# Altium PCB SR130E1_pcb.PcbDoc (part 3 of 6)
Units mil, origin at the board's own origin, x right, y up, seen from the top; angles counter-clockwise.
Board outline 5700 x 4800 mil, 6 copper layers (Top Layer, Signal Layer 1, Signal Layer 2, Signal Layer 3, Signal Layer 4, Bottom Layer), stack 61.4 mil thick; 452 components, 288 nets, 1391 pads, 911 vias.
Unrouted connection lines stored in the file: 523.
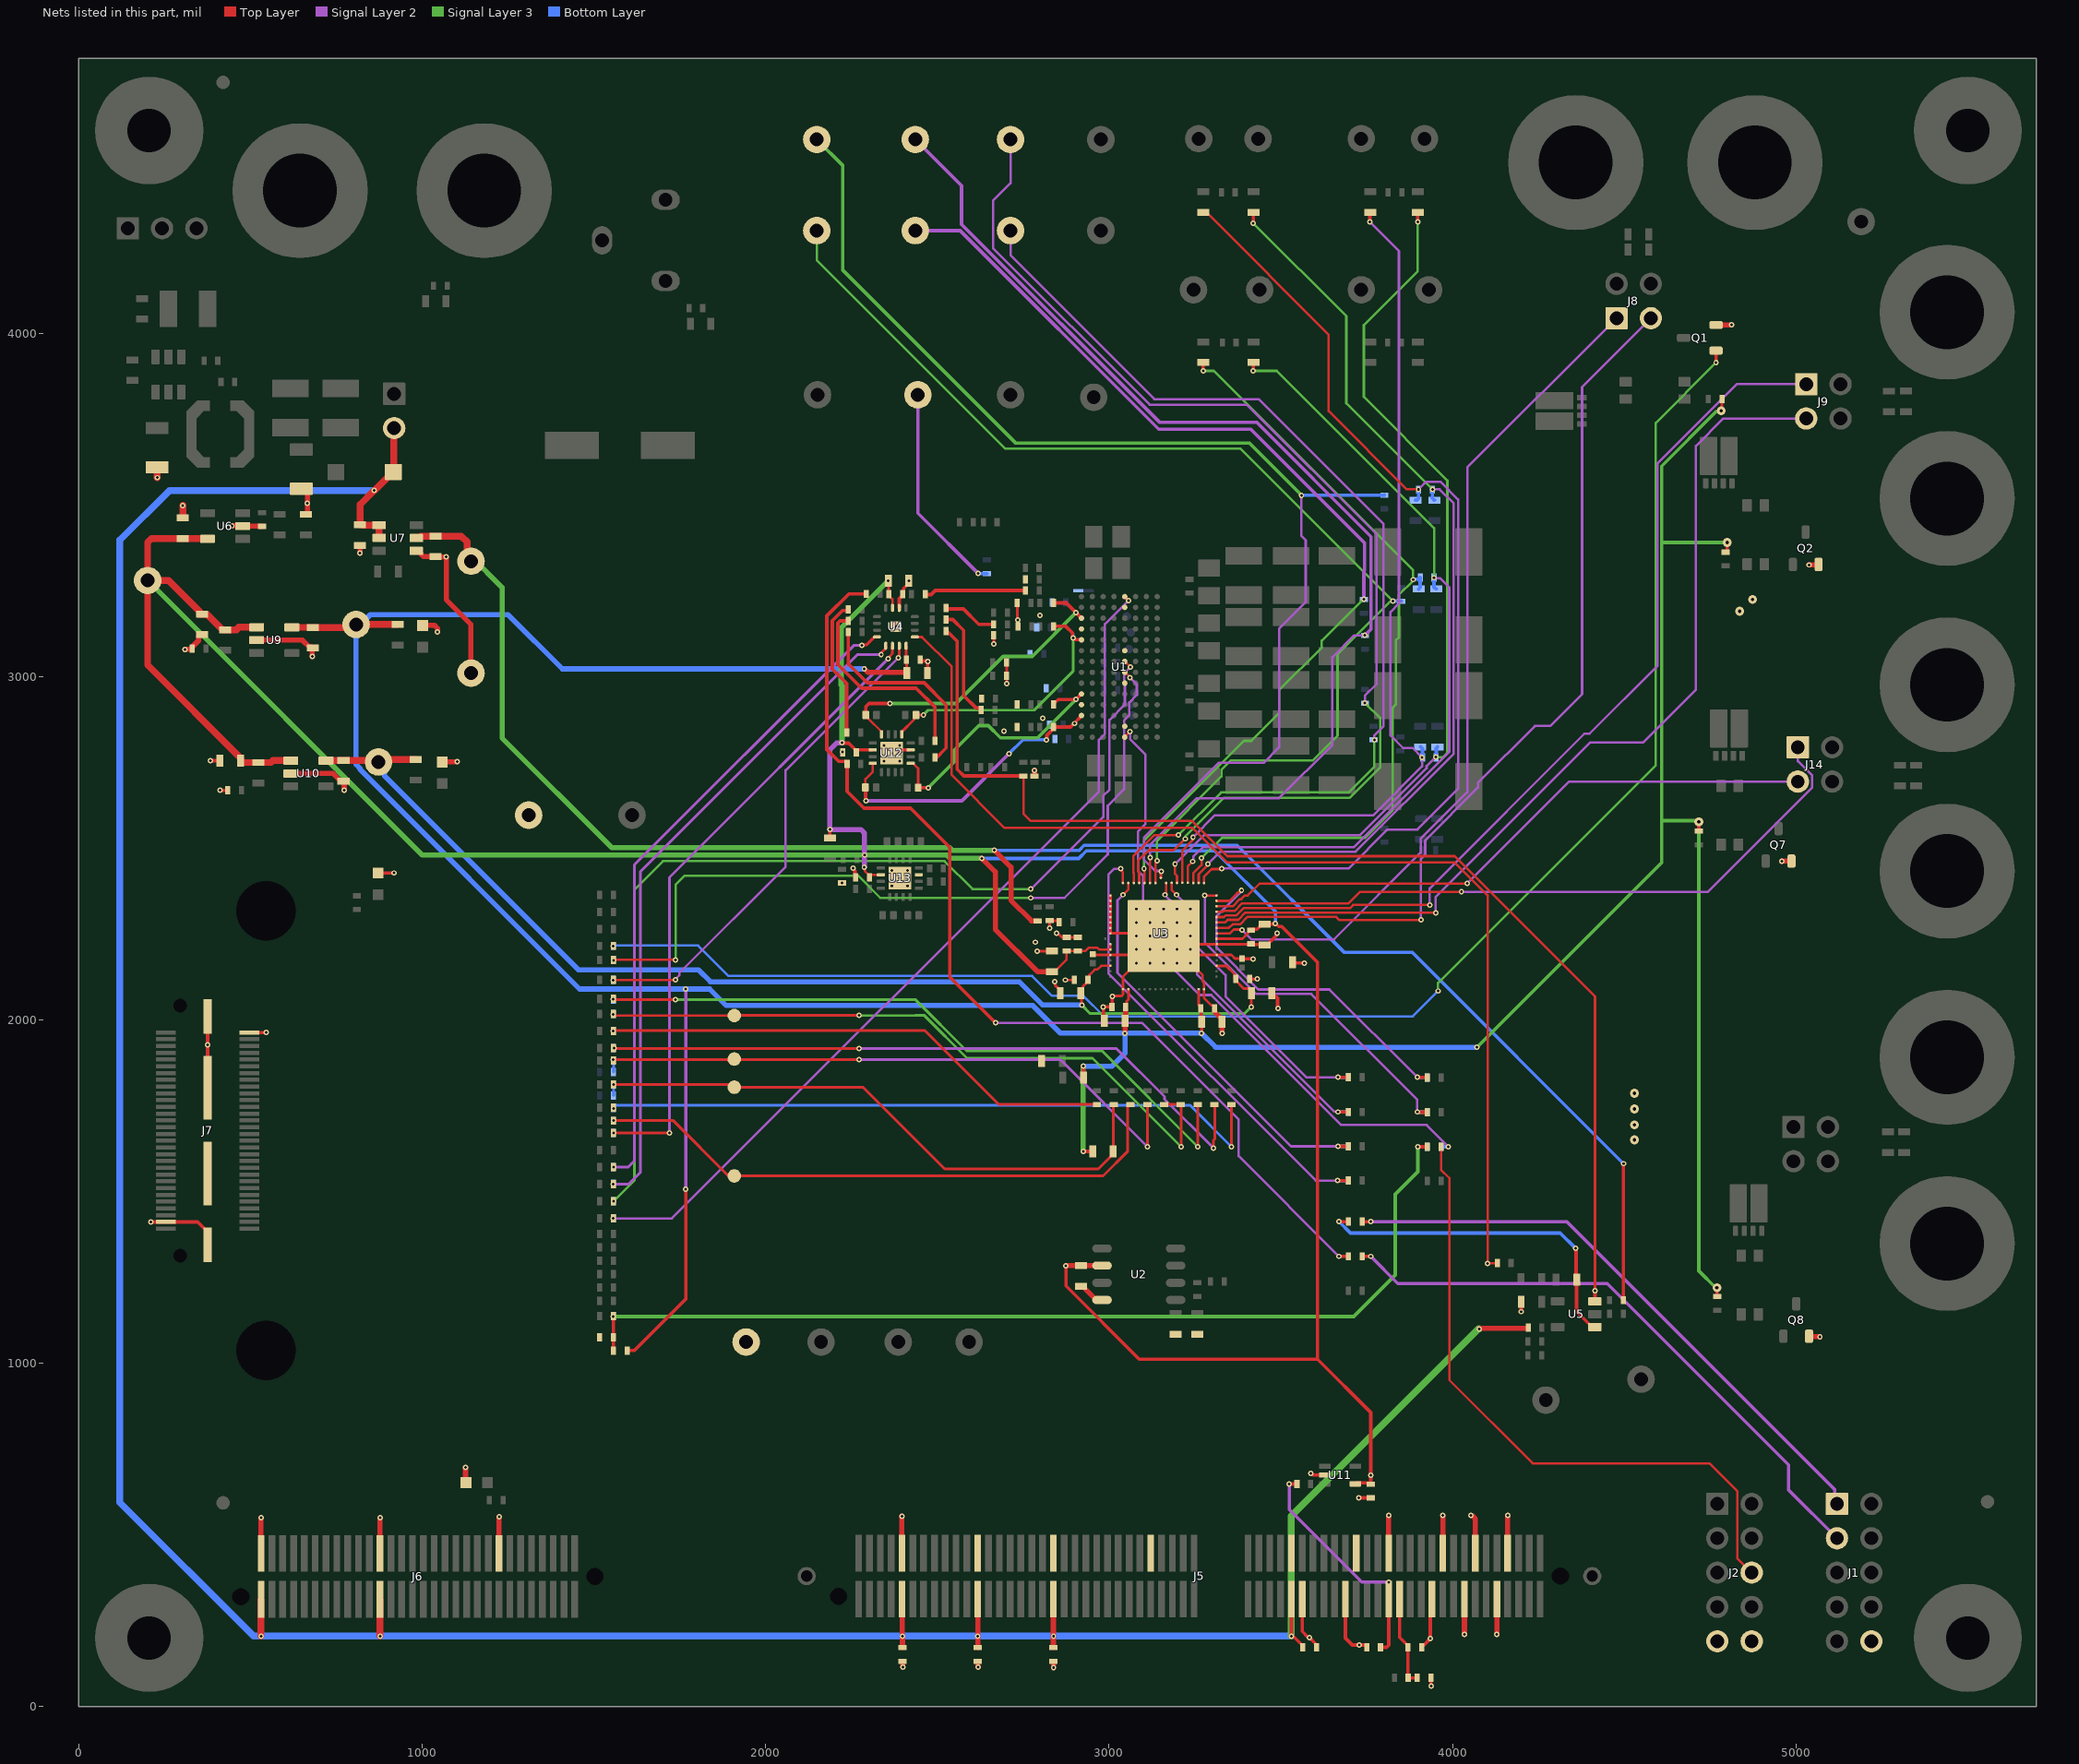
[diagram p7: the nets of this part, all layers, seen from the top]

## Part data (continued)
R116 R117 R118 R119 R120 R121 R122 R123 R124 R125 R126 R127 R128 R129 R130 R131 R132 R133 R134 R135 R136 R138 R139 R140 R141 R142 R143 R144 R145 R149 R150 R151 R152 R153 R154 R155 R156 R157 R158 R159 R160 R161 R162 R163 R164 R165 R166 R167 R168 R170 R171 R172 R173 R174 R175 R176: library part CMP-0026880-3, "RES, 22, 5%, 0.063 W, AEC-Q200 Grade 0, 0402", Manufacturer=Vishay-Dale, Power_W=63mW, Supplier Part Number 1=541-22JCT-ND, TempCo="200 ppm/C", Tolerance_%=5%, Value2=0.063W, Value_Code=22R0, ValueDisplayed=22
R137 R147 R148 R169: library part CMP-0026770-1, "RES, 1.00 k, 0.1%, 0.063 W, 0402", Manufacturer=Panasonic, Power_W=63mW, Supplier Part Number 1=P1.0KDCCT-ND, TempCo="25 ppm/C", Tolerance_%=0.1%, Value2=0.063W, Value_Code=1k00, ValueDisplayed=1.00k
R146: library part CMP-0026805-1, "RES, 2.74 k, 0.1%, 0.063 W, 0402", Manufacturer="TT Electronics/IRC", Power_W=63mW, TempCo="10 ppm/C", Tolerance_%=0.1%, Value2=0.063W, Value_Code=2k74, ValueDisplayed=2.74k
R179 R180 R181 R182: library part CMP-0026022-3, "RES, 150, 1%, 0.063 W, AEC-Q200 Grade 0, 0402", Manufacturer=Vishay-Dale, Power_W=63mW, Supplier Part Number 1=541-150LCT-ND, TempCo="100 ppm/C", Tolerance_%=1%, Value2=0.063W, Value_Code=150R, ValueDisplayed=150
R188: library part CMP-0026581-2, "RES, 866, 1%, 0.063 W, AEC-Q200 Grade 0, 0402", Manufacturer=Vishay-Dale, Power_W=63mW, Supplier Part Number 1=541-866LCT-ND, TempCo="100 ppm/C", Tolerance_%=1%, Value2=0.063W, Value_Code=866R, ValueDisplayed=866
SH-J1 SH-J2 SH-J3 SH-J4 SH-J5 SH-J6 SH-J7 SH-J8 SH-J9 SH-J10: library part CMP-0003761-2, "Shunt, 2.54mm, Gold, Black", Manufacturer="Wurth Elektronik", Supplier Part Number 1=732-2678-ND
TP1 TP5 TP8 TP12 TP26 TP27 TP29 TP30 TP31 TP32: library part CMP-0055137-2, "Test Point, Miniature, Red, TH", Color=Red, Manufacturer="Keystone Electronics", Supplier Part Number 1=36-5000-ND
TP2 TP6 TP9 TP10 TP11 TP13 TP18 TP19 TP20 TP21 TP28 TP33 TP34 TP35 TP36 TP37 TP38: library part CMP-0055138-2, "Test Point, Miniature, Black, TH", Color=Black, Manufacturer="Keystone Electronics", Supplier Part Number 1=36-5001-ND
TP3 TP7 TP14 TP15 TP16 TP17: library part CMP-0055141-2, "Test Point, Miniature, Yellow, TH", Color=Yellow, Manufacturer="Keystone Electronics", PartNumber=5004, Supplier Part Number 1=36-5004-ND
TP4: library part CMP-0055138-2, "Test Point, Miniature, Black, TH", Color=Black, Manufacturer="Keystone Electronics", PartNumber=5001, Supplier Part Number 1=36-5001-ND
TP22 TP23 TP24 TP25: library part CMP-0003825-1, "1mm Test Point, SMT", Manufacturer=Any
U1: library part CMP-0123459-1, Manufacturer="Texas Instruments", Operating Temperature Range=to
U2: library part CMP-0032601-1, "Low Noise, Very Low Drift, Precision Voltage Reference, -40 to 125 degC, 8-pin SOIC (D), Green (RoHS & no Sb/Br)", Manufacturer="Texas Instruments", Rating=Catalog, Temp Coeff(Max)(ppm/ degree C)=3
U3: library part CMP-0124125-1, "16-Channel, 16-Bit, 1-MSPS Simultaneous-Sampling SAR ADC with Bipolar Inputs on a Single Supply", Manufacturer="Texas Instruments", Max Supply Voltage=5.25V, Min Supply Voltage=1.75V, Operating Temperature Range="-40°C to +125°C"
U4: library part CMP-0084837-1, "8-Channel, True 16-Bit, SPI, Voltage-Output DAC With Precision Internal Reference, RTE0016D (WQFN-16)", Alternate Manufacturer="Texas Instruments", Alternate PartNumber=DAC80508MRTER, Operating Temperature Range="-40 to 125 C", Rating=Catalog
U5: library part CMP-0040539-2, "Precision, Rail-to-Rail Input/Output, Low Offset Voltage, Low Input Bias Current Op Amp with E-trim, 4.5 to 36 V, -40 to 125 degC, 8-Pin SOT-23 (DBV), Green (RoHS & no Sb/Br), Tape and Reel", Temperature Max="125 degC", Temperature Min="-40 degC"
U6: library part CMP-0091339-1, "300-mA, ultra-low-noise, low-IQ, low-dropout (LDO) linear regulator with high PSRR 5-SOT-23 -40 to 125", Dropout Voltage=140mV, Manufacturer="Texas Instruments", Max Supply Voltage=6V, Min Supply Voltage=1.6V, Mouser Part Number=595-TPS7A2050PDBVR, Nominal Supply Current=6.5uA, Operating Temperature Range="-40°C to +125°C", Output Voltage=5V
U7: library part CMP-0072146-1, "Switched Capacitor Voltage Converter, 6-pin SOT-23", Manufacturer="Texas Instruments", PackageTopMarking=S03A*XTT, PartNumber=LM2664M6/NOPB, PowerWise=N
U8: library part CMP-0093105-2, "Buck Converter, Adjustable, 4V-36V Input, 1-28V 1A Output, SOT23-6", Manufacturer="Texas Instruments", Max Supply Voltage=36V, Min Supply Voltage=4V, Nominal Supply Current=80uA, Operating Temperature Range="-40°C to +150°C", Output Voltage=1-28V, Switching Frequency=700kHz
U9: library part CMP-0092532-1, "300-mA, Ultra-Low-Noise, Low-IQ, High PSRR LDO", Digikey Part Number=296-TPS7A2033PDBVRCT-ND, Dropout Voltage=145mV, Manufacturer="Texas Instruments", Max Supply Voltage=6V, Min Supply Voltage=1.6V, Mouser Part Number=595-TPS7A2033PDBVR, Nominal Supply Current=6.5uA, Operating Temperature Range="-40°C to +125°C", Output Voltage=3.3V
U10: library part CMP-0095212-1, "Linear Voltage Regulator IC Positive Fixed 1 Output 300mA SOT-23-5", Digikey Part Number=296-TPS7A2018PDBVRCT-ND, Dropout Voltage=690mV, Manufacturer="Texas Instruments", Max Supply Voltage=6V, Min Supply Voltage=1.6V, Mouser Part Number=595-TPS7A2018PDBVR, Nominal Supply Current=6.5-2000uA, Operating Temperature Range="-40°C to +125°C", Output Voltage=1.8V
U11: library part CMP-0013250-3, "TMP235DCK, DCK0005A (SOT-5)", Manufacturer="Texas Instruments"
U12 U13: library part CMP-0123533-1, "Quad 1-MHz, 40-V rail-to-rail input/output, low-offset-voltage, low-power op amp 16-WQFN -40 to 125", Digikey Part Number=296-OPA4990IRTERCT-ND, Input Bias Current=10pA, Input Offset Voltage=0.3mV, Manufacturer="Texas Instruments", Max Dual Supply Voltage=20V, Max Supply Voltage=40V, Min Dual Supply Voltage=1.35V, Min Supply Voltage=2.7V, Mouser Part Number=595-OPA4990IRTER, Nominal Supply Current=120uA, Operating Temperature Range="-40°C to +125°C", Output Current Per Channel=80mA, Voltage Gain=145dB
ZZ1: library part CMP-0003616-3
ZZ2: library part CMP-0077236-1
ZZ3: library part CMP-0077237-1
ZZ4: library part CMP-0077238-1

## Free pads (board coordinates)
  round 25 smd far side mask+1.97: 2(3052.27,3175.01) 2(3057.91,3079.86) 2(3063.58,3128.37) 2(3065.52,2919.41) 2(3067.43,2886.51) 2(3073.81,2951.75)

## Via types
v1: diameter 26, hole 10, Top Layer to Bottom Layer, tented both sides, 435 vias
v2: diameter 16, hole 8, Top Layer to Bottom Layer, tented both sides, 208 vias
v3: diameter 16, hole 8, Top Layer to Bottom Layer, 145 vias
v4: diameter 16, hole 8, Top Layer to Bottom Layer, tented bottom, 46 vias
v5: diameter 19.68, hole 8, Top Layer to Bottom Layer, tented both sides, 35 vias
v6: diameter 17, hole 8, Top Layer to Bottom Layer, 30 vias
v7: diameter 18, hole 8, Top Layer to Bottom Layer, tented both sides, 6 vias
v8: diameter 16, hole 8, Top Layer to Bottom Layer, tented top, 4 vias
v9: diameter 19.68, hole 8, Top Layer to Bottom Layer, 1 vias
v10: diameter 17, hole 8, Top Layer to Bottom Layer, tented both sides, 1 vias

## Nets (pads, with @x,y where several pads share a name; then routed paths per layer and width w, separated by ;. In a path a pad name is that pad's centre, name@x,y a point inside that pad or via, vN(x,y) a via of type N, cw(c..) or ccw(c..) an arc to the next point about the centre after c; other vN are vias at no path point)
1V8A: C80.2 C81.2 C82.2 C83.1 C108.1 R115.2 TP32.1 U3.30 U3.51 U10.5 | length 3491.6
  Top Layer w7: C81.2@2938.7,2116.06 2942.7,2120.06 2942.7,2130.43 2958.78,2146.51 2966.03,2146.51 2976.97,2157.44 U3.30@3004.17,2157.44
  Top Layer w8: v3@2920.24,2042.59 v3(2920.7,2043.06) 2919.41,2044.34 2919.41,2076.55 C82.2@2918.12,2077.84 2924.12,2083.84 2924.12,2096.98 2938.7,2111.56 C81.2@2938.7,2116.06 ; U3.51@3313.22,2157.44 3341.14,2157.44 3365.55,2133.03 3365.55,2117.73 3392.73,2090.55 3408.45,2090.55 3414.45,2084.55 C83.1@3414.45,2077.05 3414.09,2076.68 3414.09,2038.01 v3(3413.73,2037.65)
  Top Layer w20: U10.5@720.06,2754.8 763.55,2754.8 C108.1@771.06,2754.82 869.02,2754.82 TP32.1@872.97,2750.87 880.34,2758.23 R115.2@981.48,2758.23
  Signal Layer 3 w8: v3(2920.7,2043.06) 2945.7,2018.06 3394.13,2018.06 v3(3413.73,2037.65)
  Bottom Layer w15: TP32.1@872.97,2750.87 872.97,2733.28 890.58,2715.67 890.58,2710.08 1455.16,2145.5 1804.53,2145.5 1839.22,2110.81 2738.75,2110.81 2806.5,2043.06 v3(2920.7,2043.06)
3V3D: C71.2 C74.2 C76.2 C77.2 C90.1 C91.2 C103.1 R86.1 R88.2 R111.2 R178.2 R179.2 R180.2 R181.2 R182.2 TP31.1 U3.34 U3.47 U4.16 U9.5 | length 11955.4
  Top Layer w7: U3.47@3261.06,2089.53 3261.06,2043.59 3267,2037.65 C76.2@3267,2033.15
  Top Layer w8: U4.16@2409,3089.49 2409.28,3089.21 2409.28,3049.85 C90.1@2410.29,3048.84 2410.72,3048.41 2410.72,3010.42 C91.2@2411.15,3009.99 ; C77.2@3048.63,2037.84 3052.13,2041.34 3052.13,2054.62 3056.34,2058.83 U3.34@3056.34,2089.53 ; v1(4782.65,3773.82) 4783.94,3775.12 4783.94,3806.94 R179.2@4785.24,3808.24
  Top Layer w10: R178.2@1597.16,1036.74 1599.29,1036.74 1599.66,1037.1 1617.8,1037.1 1767.74,1187.04 v3(1767.74,1506.65) ; v2(2924.73,1616.77) R88.2@2952.43,1616.77 ; v2(2924.76,1864.81) 2925.05,1864.52 2925.05,1831.72 R86.1@2925.34,1831.43 ; C76.2@3267,2033.15 3268.22,2031.93 3268.22,1995.14 C74.2@3269.45,1993.92 3269.57,1993.79 3269.57,1961.18 v2(3269.7,1961.06) ; R181.2@4717.32,2549.51 v1(4717.32,2576.97) ; v1(4770,1220) 4770.51,1219.49 4770.51,1195.07 R182.2@4771.02,1194.56 ; R180.2@4794.85,3362.02 4797.5,3362.02 4800,3364.52 v1(4800,3390)
  Top Layer w15: v4(2287.75,3021.94) 2288.02,3021.94 2298.02,3011.93 2408.65,3011.93 2410.16,3010.42 C91.2@2410.72,3010.42 ; v2(3046.7,1961.06) C71.2@3046.7,1997.06 3048.63,1998.99 C77.2@3048.63,2037.84
  Top Layer w20: U9.5@620.56,3143.26 620.82,3143 681.75,3143 C103.1@682.01,3142.73 799.1,3142.73 TP31.1@807.72,3151.35 921.5,3151.35 921.88,3151.73 R111.2@929.38,3151.73
  Signal Layer 2 w10: v3(1767.74,1506.65) v2(1767.74,2089.81)
  Signal Layer 3 w10: v2(4070.97,1920) 4608.97,2458 4608.97,2580 ; v1(4770,1220) 4766.14,1220 4717.32,1268.83 4717.32,2170.52 v1(4717.32,2576.97) 4715.21,2579.07 4707.43,2579.07 4706.51,2580 4608.97,2580 ; v1(4782.65,3773.82) 4779.58,3770.76 4767.14,3770.76 4608.97,3612.59 4608.97,3390 ; v1(4800,3390) 4608.97,3390 ; 4608.97,2580 4608.97,3390
  Signal Layer 3 w15: v2(2924.73,1616.77) v2@2924.75,1864.79
  Bottom Layer w15: v4(2287.75,3021.94) 1408.06,3021.94 1250,3180 849.01,3180 820.36,3151.35 TP31.1@807.72,3151.35 807.72,2743.99 819.47,2732.24 819.47,2728.71 1458.37,2089.81 1837.59,2089.81 1885.56,2041.84 2778.01,2041.84 2858.8,1961.06 v2(3046.7,1961.06) ; v2(2924.76,1864.81) 3008.09,1864.81 3046.7,1903.42 v2(3046.7,1961.06) ; v2(4070.97,1920) 3310.75,1920 v2(3269.7,1961.06) v2(3046.7,1961.06)
5V2: C95.2 C112.2 C113.2 C114.2 C115.2 J4.2 J5.48 J5.84 J5.98 J5.112 J6.158 J6.180 L1.1 R102.2 U7.4 U7.5 | length 9656.3
  Top Layer w10: J5.112@2397.12,313.07 J5.112@2397.93,312.27 ; C115.2@2397.93,173 C115.2@2398.73,172.2 ; J5.98@2617.6,313.07 J5.98@2617.81,312.86 ; C114.2@2617.81,172.41 C114.2@2618.02,172.2 ; C113.2@2837.69,172.2 C113.2@2837.88,172.39 ; J5.84@2837.88,312.88 J5.84@2838.07,313.07 ; J5.48@3530.98,313.07 3530.98,205.61 3532.13,204.47 3536.87,204.47 3564.24,177.1 C112.2@3564.24,173.04 ; v2(4078.15,1100) v2@4079.3,1101.15 ; R102.2@4217.95,1101.15 4220.45,1103.65 R102.2@4220.45,1104
  Top Layer w15: C115.2@2397.93,172.2 2398.6,172.2 2398.6,205.34 2398.28,205.66 2398.28,311.91 J5.112@2397.93,312.27 ; C114.2@2617.81,172.2 C114.2@2618.02,172.2 v2(2618.02,205.34) 2617.83,205.53 J5.98@2617.83,312.83 ; C113.2@2837.88,172.2 2837.88,204.39 2838.56,205.07 2838.56,205.61 2837.88,206.3 J5.84@2837.88,312.88 ; v2@4079.3,1101.15 R102.2@4217.95,1101.15
  Top Layer w20: v2(531.13,205.5) J6.180@531.13,312.2 ; U7.5@874.95,3403.33 U7.4@874.95,3440.73 827.13,3440.73 826.59,3441.28 C95.2@819.09,3441.28 819.09,3500.38 v2(860.22,3541.51) 861.05,3541.51 915.06,3595.53 L1.1@916.05,3595.53 917.35,3596.83 917.35,3721.88 J4.2@918.65,3723.18 ; v2(877.59,205.5) J6.158@877.59,312.2
  Signal Layer 3 w20: v2(3530.71,205.34) 3530.71,555.3 4075.41,1100 v2(4078.15,1100)
  Bottom Layer w20: v2(860.22,3541.51) 264.55,3541.51 120,3396.97 120,594.56 509.06,205.5 v2(877.59,205.5) ; v2(877.59,205.5) v2(2398.47,205.47) 2398.66,205.34 v2(2618.02,205.34) v2(2838.56,205.34) v2(3530.71,205.34) v2@3530.98,205.61
5VA: C68.1 C70.1 C73.2 C75.2 C78.2 C79.2 C88.2 C89.1 C94.1 C98.1 C106.1 C109.2 C126.2 C127.2 R108.1 R114.1 R187.1 TP29.1 U2.2 U3.26 U3.27 U3.56 U4.7 U6.5 U9.1 U10.1 U11.4 U12.2 U13.2 | length 10156.2
  Top Layer w7: v2(2287.75,2444.27) 2288.89,2443.13 2288.89,2433.64 2302.79,2419.74 C127.2@2302.79,2415.24 2302.79,2418.62 2306.79,2422.62 U13.2@2335.79,2422.62 ; v4(2357.09,3278.87) 2358.28,3277.68 2358.28,3240.95 C89.1@2359.47,3239.75 2359.47,3235.25 2369.63,3225.1 U4.7@2369.63,3199.73 ; C70.1@2841.2,2140.06 2869.39,2168.25 2876.37,2175.23 C78.2@2876.37,2200.07 C79.2@2908.8,2200.07 ; C79.2@2907.4,2198.67 C79.2@2908.8,2200.07 ; U3.26@3004.17,2220.43 U3.27@3004.17,2204.68 2971.23,2204.69 2966.31,2209.6 2940.49,2209.6 2930.96,2200.07 C79.2@2908.8,2200.07
  Top Layer w8: U3.56@3313.22,2236.18 3388.47,2236.18 3405.63,2253.35 3405.63,2257.85 3409.13,2261.35 C75.2@3413.63,2261.35
  Top Layer w10: R187.1@2187.16,2529.47 2187.27,2529.58 v2(2187.27,2554.06) ; v2(2222.65,2806.74) 2223.8,2805.6 2242.39,2805.6 2261.72,2786.27 2261.72,2781.77 C126.2@2264.22,2779.27 ; C126.2@2264.41,2779.08 2264.41,2783.73 2266.72,2786.04 2311.91,2786.04 U12.2@2312.18,2786.32 ; v3(2874.65,1283.83) 2874.65,1225.18 3088.14,1011.7 3606.81,1011.7 ; C75.2@3409.13,2261.35 3411.63,2263.85 3430.99,2263.85 3445.2,2278.05 C73.2@3452.7,2278.05 3453.65,2279 3483.54,2279 v3(3484.49,2279.95) 3486.12,2279.95 3494.35,2271.71 3502.74,2271.71 3548.56,2225.9 3606.81,2167.64 3606.81,1011.7 ; U11.4@3717.33,648.67 3720.2,651.54 C109.2@3761.88,651.54 ; C109.2@3761.88,648.03 C109.2@3761.88,651.54 ; 3606.81,1011.7 3761.88,856.63 v3(3761.88,674.26) C109.2@3761.88,651.54
  Top Layer w15: v3(2629.69,2470.18) 2668.98,2430.89 2668.98,2263.3 2792.22,2140.06 C70.1@2841.2,2140.06 ; v3(2874.65,1283.83) 2874.69,1283.87 2918.94,1283.87 2919.09,1284.02 2979.57,1284.02 U2.2@2979.68,1284.14
  Top Layer w20: U6.5@375.14,3400.62 373.67,3402.1 C94.1@303.39,3402.1 212.5,3402.1 200.79,3390.38 TP29.1@200.79,3279.56 ; U9.1@518.19,3143.26 466.54,3143.26 459.14,3135.86 R108.1@426.32,3135.86 418.82,3135.86 372.95,3181.73 C98.1@359.28,3181.73 351.78,3181.73 351.78,3189.23 261.44,3279.56 TP29.1@200.79,3279.56 ; U10.1@617.7,2754.8 566.04,2754.8 560.61,2749.37 R114.1@522.97,2749.37 471.61,2749.37 C106.1@471.61,2754.8 471.61,2762.3 200.79,3033.12 TP29.1@200.79,3279.56
  Signal Layer 2 w15: v2(2222.65,2806.74) 2207.43,2806.74 2187.27,2786.58 v2(2187.27,2554.06) 2277.34,2554.06 2287.87,2543.53 v2(2287.87,2479.98) 2287.81,2479.92 2287.81,2444.34 v2(2287.75,2444.27)
  Signal Layer 3 w15: TP29.1@200.79,3279.56 1000.37,2479.98 v2(2287.87,2479.98) ; v2(2222.65,2806.74) 2222.65,2973.07 2220,2975.73 2220,3141.78 v4(2357.09,3278.87) ; v2@2287.87,2480.44 2288.33,2479.98 2527.8,2479.98 2537.6,2470.18 v3(2629.69,2470.18)
  Bottom Layer w10: v3(2629.69,2470.18) 2912.11,2470.18 2933.94,2492.01 3307.64,2492.01 3484.49,2315.16 v3(3484.49,2279.95)
-5V: C101.2 R89.2 R106.2 TP30.1 U7.2 | length 5241.2
  Top Layer w10: R106.2@4497.78,1183.62 v2(4497.78,1581.22)
  Top Layer w15: v4(2665.57,2493.68) 2714.7,2444.55 2714.7,2348.01 2774.4,2288.31 R89.2@2792.79,2288.31
  Top Layer w20: U7.2@983.22,3403.33 991.09,3403.33 996.56,3408.8 C101.2@1039.09,3408.8 1114.09,3408.8 1130.91,3391.98 1130.91,3346.99 TP30.1@1142.39,3335.51
  Signal Layer 3 w15: TP30.1@1142.39,3349.89 1232.99,3259.28 1232.99,2821.04 1552.56,2501.48 2536,2501.48 2543.8,2493.68 v4(2665.57,2493.68)
  Bottom Layer w10: v4(2665.57,2493.68) 2912.98,2493.68 2927.31,2508.01 3373.24,2508.01 3684.41,2196.84 3882.15,2196.84 v2(4497.78,1581.22)
ADC_CONVST: R83.2 R139.2 R156.1 | length 1975.5
  Top Layer w8: R156.1@1557.16,1744.16 R156.1@1558.97,1742.35 ; R83.2@3355.89,1753.45 3356.48,1752.86 v4(3356.48,1630.49)
  Bottom Layer w8: R139.2@1558,1748.99 1560.66,1751.65 3235.31,1751.65 v4(3356.48,1630.49)
  other v3: 1557.99,1741.38
ADC_CSn: R79.2 R88.1 R123.1 R126.1 R157.1 TP25.1 | length 1757.3
  Top Layer w8: R157.1@1557.09,1811.96 v3(1557.16,1811.96) ; R157.1@1557.16,1807.4 v3(1557.16,1811.96) ; R79.2@3013.73,1753.45 3012.43,1752.15 R88.1@3012.43,1616.77 3012.43,1609.27 2968.83,1565.67 2521.74,1565.67 2283.75,1803.66 1900.45,1803.66 1892.14,1811.96 v3(1557.16,1811.96)
  Bottom Layer w8: R123.1@1557.16,1779.39 v3(1557.16,1811.96)
ADC_DRDY: R82.2 R127.1 R159.1 | length 2003.5
  Top Layer w8: R159.1@1557.16,1917.93 1558.4,1916.69 v3(2271.94,1916.69) ; v4(3303.75,1626.64) 3303.75,1648.8 3307.6,1652.64 3307.6,1752.86 R82.2@3307.01,1753.45
  Signal Layer 2 w8: v3(2271.94,1916.69) 3021.39,1916.69 3161.42,1776.66 3161.42,1768.97 v4(3303.75,1626.64)
  Bottom Layer w8: R127.1@1558.13,1918.91 R127.1@1560.34,1916.69
  other v3: 1559.24,1917.8
ADC_RSTn: R84.2 R128.1 R160.1 | length 1497.2
  Top Layer w8: R160.1@1557.16,1967.49 1558.13,1968.46 1730,1968.46 2464.62,1968.46 2679.63,1753.45 R84.2@2964.85,1753.45
  other v3: 1556.67,1967
ADC_SCLK: R76.2 R122.1 R125.1 R158.1 TP22.1 | length 1813.8
  Top Layer w8: R158.1@1556.32,1883.86 1888.57,1883.86 TP22.1@1897.87,1874.56 ; TP22.1@1908.94,1885.63 1909.82,1884.75 2271.06,1884.75 v3(2271.94,1883.86) ; R76.2@3111.49,1753.45 3112.08,1752.86 v4(3112.08,1630.49)
  Signal Layer 2 w8: v3(2271.94,1883.86) 2858.7,1883.86 v4(3112.08,1630.49)
  Bottom Layer w8: R122.1@1557.16,1847.46 R125.1@1557.16,1883.86
  other v3: 1556.9,1883.86
ADC_SDI: R77.2 R120.1 R155.1 TP23.1 | length 1736.8
  Top Layer w8: R155.1@1557.16,1706.1 1558.3,1707.24 1730,1707.24 1891.78,1545.46 2982.77,1545.46 3054.61,1617.31 3054.61,1749.95 3058.11,1753.45 R77.2@3062.61,1753.45
  other v3: 1557.43,1706.27
ADC_SDOA: R78.2 R81.2 R121.1 R161.1 TP24.1 | length 1991.4
  Top Layer w8: R161.1@1557.16,2017.05 R161.1@1557.16,2016.05 ; R161.1@1560.66,2012.55 R161.1@1557.16,2016.05 ; v4(2271.94,2012.55) 1908.98,2012.53 TP24.1@1908.94,2012.51 1560.66,2012.48 1557.16,2015.98 R161.1@1557.16,2016.05 ; R78.2@3160.96,1752.86 R78.2@3160.37,1753.45 R81.2@3209.25,1753.45 3209.84,1752.86 v4(3209.84,1630.49)
  Signal Layer 3 w8: v4(2271.94,2012.55) 2272,2012.48 2436.76,2012.48 2436.83,2012.55 2462.58,2012.55 2586.66,1888.47 2951.85,1888.47 v4(3209.84,1630.49)
  other v3: 1556.18,2016.07
ADC_SDOB: R80.2 R124.1 R162.1 | length 2002.3
  Top Layer w8: R162.1@1557.16,2059.2 v4(1738,2059.2) ; R80.2@3258.13,1753.45 3258.72,1752.86 v4(3258.72,1630.49)
  Signal Layer 3 w8: v4(1738,2059.2) 2435.73,2059.2 2585.37,1909.56 2979.64,1909.56 v4(3258.72,1630.49)
  other v3: 1556.18,2059.96
AGND: C1.2 C2.2 C3.2 C4.2 C9.2 C11.2 C12.2 C17.2 C68.2 C69.2 C70.2 C71.1 C72.2 C73.1 C74.1 C75.1 C76.1 C77.1 C78.1 C79.1 C80.1 C81.1 C82.1 C83.2 C84.1 C85.2 C86.2 C87.2 C88.1 C89.2 C90.2 C91.1 C92.2 C93.1 C94.2 C95.1 C98.2 C100.1 C101.1 C103.2 C106.2 C107.1 C108.2 C109.1 C110.2 C111.1 C112.1 C113.1 C114.1 C115.1 C126.1 C127.1 D1.1 D2.1 D3.1 D4.1 J1.10 J2.9 J2.10 J5.7 J5.10 J5.13 J5.16 J5.19 J5.22 J5.29 J5.35 J5.38 J5.46 J5.47 J5.65 J5.83 J5.97 J5.111 J6.135 J6.157 J6.179 J7.3 J7.60 J7.MP1 J7.MP2 J7.MP3 J7.MP4 NT1.2 Q1.2 Q2.2 Q7.2 Q8.2 R1.1 R2.1 R7.1 R8.1 R13.1 R27.1 R30.1 R33.1 R38.1 R85.2 R87.2 R100.1 R112.1 R113.2 R147.2 R177.1 R188.1 TP4.1 TP33.1 TP34.1 TP38.1 U1.A4 U1.A11 U2.4 U3.17 U3.18 U3.19 U3.20 U3.21 U3.22 U3.23 U3.24 U3.28 U3.33 U3.48 U3.53 U3.55 U3.65 U4.6 U4.17 U6.2 U7.1 U9.2 U10.2 U11.2 U12.11 U12.17 U13.11 U13.17 | length 6520.9
  Top Layer w7: v5(3237.44,2165.31) 3272.89,2129.86 3272.89,2111.66 3276.81,2107.75 3276.81,2063.34 3298.5,2041.65 3303,2041.65 3307,2037.65 C76.1@3307,2033.15
  Top Layer w8: v2(2664.07,3094.39) R30.1@2664.07,3119.58 ; v2(2701.65,2979.34) R1.1@2701.65,3040.57 ; C2.2@2732.42,3214 2733.67,3212.75 2733.67,3165.8 v2(2734.92,3164.55) ; C11.2@2734.95,3145.59 v2(2734.92,3164.55) ; v3(2791.08,2199.8) 2791.21,2199.93 2833.57,2199.93 C70.2@2833.7,2200.06 ; v2(2826.58,2267.29) 2826.58,2288.94 C84.1@2826.7,2289.06 2849.08,2289.06 R85.2@2852.57,2285.57 ; v3(2841.59,2111.73) 2843.88,2109.44 2843.88,2099.58 2858.12,2085.34 C82.1@2858.12,2077.84 ; v3(2847.05,2252.71) 2850.29,2252.71 2862.94,2240.07 C78.1@2876.37,2240.07 C79.1@2908.8,2240.07 ; v3(2872.62,2115.94) 2898.58,2115.94 C81.1@2898.7,2116.06 ; C87.2@2950.7,2188.06 2951.58,2188.94 3064.21,2188.94 v5(3079.96,2204.68) ; U3.17@3004.17,2362.17 U3.18@3004.17,2346.42 U3.19@3004.17,2330.67 U3.22@3004.17,2283.43 U3.24@3004.17,2251.93 3072.08,2251.93 v5(3079.96,2244.06) ; v3(3010,2067.66) 3011.53,2069.19 3035.9,2069.19 3040.59,2073.88 3040.59,2125.94 v5(3079.96,2165.31) ; v5(3237.44,2204.68) 3253.19,2188.94 3356.19,2188.94 3366.82,2178.31 C85.2@3387.09,2178.31 ; v5(3237.44,2244.06) 3237.44,2242.22 3259.23,2220.43 U3.55@3313.64,2220.43 C75.1@3412.72,2220.43
  Top Layer w10: v2(210,1411.46) J7.3@254,1411.46 346.3,1411.46 375.5,1382.26 J7.MP1@375.5,1344.76 ; J7.MP3@375.5,1802.26 v2(375.5,1927.58) J7.MP4@375.5,2009.76 ; v2(383,2754.8) C106.2@411.61,2754.8 ; v2(412.29,2668.34) v2(412.29,2668.34) 434.04,2668.29 C107.1@434.09,2668.25 ; J7.60@497,1963.06 497.04,1963.03 v2(545.5,1962.99) v2(545.5,1962.99) ; D4.1@872.19,2427.62 v2(917.68,2427.62) ; D2.1@1058.6,2750.87 D2.1@1059.59,2751.85 ; v2(2254.58,2441.1) 2254.58,2439.47 2260.29,2433.77 2260.29,2417.74 C127.1@2262.79,2415.24 ; U4.6@2389.31,3199.73 2389.31,3226.54 2395.53,3232.75 2396.97,3232.75 2399.47,3235.25 C89.2@2399.47,3239.75 2401.97,3242.25 2401.97,3256.26 2417.09,3271.37 v4(2417.09,3278.87) ; v5(2390.14,2799.31) 2390.14,2791.55 2395.37,2786.32 U12.11@2422.42,2786.32 ; C90.2@2450.29,3048.84 2450.29,3047.23 2452.79,3044.73 2470.88,3044.73 v4(2472.03,3043.58) 2471.59,3043.15 2471.59,3010.43 C91.1@2471.15,3009.99 ; C71.1@2986.7,1997.06 2983.53,2000.22 v3(2983.53,2037.65) 2983.63,2037.75 3008.53,2037.75 C77.1@3008.63,2037.84 ; C77.1@3008.74,2037.95 3009.31,2038.53 3009.31,2066.97 v3(3010,2067.66) ; C85.2@3387.09,2178.31 3387.92,2177.48 3419.05,2177.48 v3(3419.89,2176.64) ; C80.1@3409.05,2118.73 v3(3432.12,2118.73) ; C75.1@3412.72,2220.43 C75.1@3413.63,2221.35 3415.28,2219.7 3456.55,2219.7 3459.2,2217.06 3488.36,2246.21 3488.36,2251.56 v3(3489.5,2252.71) ; C83.2@3475.95,2077.05 3476.93,2077.05 3490.64,2063.35 3490.64,2034.42 v3(3492,2033.05) ; C86.2@3536.19,2168.06 3538.93,2165.31 v3(3568.9,2165.31) ; J5.46@3562.48,313.07 3562.48,218.86 3578.92,202.42 3582.3,202.42 3601.74,182.98 3601.74,175.1 C112.1@3604.24,172.6 ; v3(3587.26,678.67) 3589.97,678.67 3594.38,674.26 U11.2@3628.75,674.26 ; J5.38@3688.46,313.07 3688.46,199.6 3708.46,179.6 3747.98,179.6 3750.48,177.1 C110.2@3750.48,172.6 ; v3(3727.26,608.03) C109.1@3761.88,608.03 ; C111.1@3910.11,172.6 3910.11,177.1 3912.61,179.6 3917.11,179.6 v2(3935.59,198.07) 3935.59,308.23 J5.22@3940.43,313.07 ; v2(3937.67,60) R147.2@3937.67,83.63 ; v2(4200,1150) v2(4200,1150) 4200.04,1179.33 R100.1@4200.08,1179.37
  Top Layer w15: v2(309.38,3078.42) 309.57,3078.61 330.42,3078.61 C100.1@330.42,3081.23 330.42,3085.73 349.28,3104.59 349.28,3119.23 351.78,3121.73 C98.2@359.28,3121.73 ; v2(446.01,3438.92) 446.2,3438.73 476.8,3438.73 U6.2@477.5,3438.02 528.44,3438.02 529.27,3437.2 C93.1@533.77,3437.2 ; U9.2@518.19,3105.86 651.38,3105.86 672.01,3085.23 679.51,3085.23 C103.2@682.01,3082.73 680.18,3080.91 680.18,3058.57 v2(679.99,3058.38) ; J6.179@531.13,446.06 v2(531.13,549.81) ; U10.2@617.7,2717.4 740.97,2717.4 761.06,2697.32 768.56,2697.32 773.14,2692.74 773.14,2668.34 v2(773.33,2668.15) ; R113.2@648.25,3546.43 656.01,3546.43 666.23,3536.22 C92.2@666.23,3472.15 ; v2(819.09,3359.02) C95.1@819.09,3381.28 ; J6.157@877.59,446.06 v2(877.59,549.9) ; U7.1@983.22,3365.92 991.09,3365.92 995.4,3361.61 995.4,3357.58 1004.19,3348.8 C101.1@1039.09,3348.8 1039.66,3348.22 1070.17,3348.22 v2(1070.36,3348.03) 1070.36,3223.48 1142.39,3151.45 TP38.1@1142.39,3009.58 ; D1.1@1001.57,3148.18 1002.36,3148.97 1035.74,3148.97 1044.79,3139.92 1044.79,3130.04 v2(1044.98,3129.85) ; D2.1@1059.59,2751.85 v2(1102.07,2751.85) ; v2(1126.12,696) 1126.32,695.81 1126.32,653.63 D3.1@1127.46,652.49 ; J6.135@1224.05,446.06 v2(1224.04,552.57) ; J5.111@2397.12,446.93 v2(2397.12,554.62) ; C115.1@2398.73,132.2 2399.42,132.2 2399.42,115.39 v2(2399.61,115.2) ; C114.1@2618.02,132.2 2618.71,132.2 2618.71,115.39 v2(2618.9,115.2) ; R33.1@2783.14,2710.14 v3(2783.14,2726.64) ; C113.1@2837.69,132.2 2838.37,132.2 2838.37,113.74 v2(2838.56,113.55) ; C68.2@2918.98,1223.91 2926.48,1223.91 2928.98,1221.41 2928.98,1218.11 2962.95,1184.14 U2.4@2979.68,1184.14 ; C76.1@3307,2033.15 3307,2023.87 3329.45,2001.42 C74.1@3329.45,1993.92 v3(3329.45,1960.26) ; J5.29@3814.45,446.93 v2(3814.45,556.62) ; J5.19@3971.93,446.93 v2(3971.93,556.43) ; v2(4034.92,210.36) J5.16@4034.92,313.07 ; v2(4054.15,556.72) 4054.34,556.52 4057.4,556.52 4066.46,547.47 4066.46,446.98 J5.13@4066.41,446.93 ; v2(4129.41,210.36) J5.10@4129.41,313.07 ; J5.7@4160.9,446.93 v2(4160.9,556.62) ; Q1.2@4767.49,4023.61 4812.18,4023.61 4812.55,4023.98 v4(4812.82,4023.98) ; v4(4958.69,2461.82) 4958.91,2462.04 4986.81,2462.04 Q7.2@4987.03,2462.26 ; v4(5038.09,3324.93) 5038.63,3325.47 5065.44,3325.47 Q2.2@5065.98,3326.01 ; Q8.2@5038.37,1078.35 5039.25,1077.47 5069.12,1077.47 v4(5070,1076.59)
  Top Layer w20: R112.1@228.34,3608.77 228.79,3608.32 v2(228.79,3578.91) ; v2(303.29,3498.06) 303.29,3462.1 C94.2@303.39,3462.1
  Signal Layer 2 w10: TP4.1@2443.41,3820.18 2443.41,3475.56 v2(2619.16,3299.8)
  Bottom Layer w10: v2(2619.16,3299.8) R13.1@2644.92,3299.8
  other v1: 4530.03,1650.36 4530.03,1693.87 4530.03,1740.36 4530.03,1785.99 4836.04,3190.09 4873.52,3224.53
  other v2: 3728.22,179.6 3583.45,201.27 2223.16,2398.62 2224.39,2779.74 2694.43,2840.45 2807.59,2878.9 2798.8,3177.67 666.23,3504.18
  other v3: 2785.7,2226.06
  other v5: 3119.33,2165.31 3158.7,2165.31 3198.07,2165.31 3119.33,2204.68 3158.7,2204.68 3198.07,2204.68 3119.33,2244.06 3158.7,2244.06 3198.07,2244.06 3079.96,2283.43 3119.33,2283.43 3158.7,2283.43 3198.07,2283.43 3237.44,2283.43 3079.96,2322.8 3119.33,2322.8 3158.7,2322.8 3198.07,2322.8 3237.44,2322.8 2368.07,2389.94 2413.74,2389.94 2390.91,2412.78 2368.07,2435.61 2413.74,2435.61 2344.47,2753.64 2390.14,2753.64 2367.3,2776.48 2344.47,2799.31
  other v9: 2379.47,3144.61
AINM1: J8.3 U3.58 | length 2667.1
  Top Layer w7: U3.58@3313.22,2267.68 3347.81,2267.68 3350.6,2270.46 3352.16,2270.46 3359.93,2278.23 3381.58,2278.23 3402.79,2299.45 3661.43,2299.45 3669.94,2290.94 v2(3908.18,2290.94)
  Signal Layer 2 w7: v2(3908.18,2290.94) 3908.18,2468.98 3920.57,2481.37 3920.57,2522.36 4074.37,2676.16 4074.37,2689.59 4240.57,2855.79 4284.5,2855.79 4377.36,2948.65 4377.36,3842.85 J8.3@4577.79,4043.27
AINM2: J9.1 U3.60 | length 2732.9
  Top Layer w7: U3.60@3313.22,2299.17 3334.62,2299.17 3339.68,2304.23 3370.81,2304.23 3392.02,2325.45 3701.75,2325.45 3710.9,2334.61 v2(3933.57,2334.61)
  Signal Layer 2 w7: v2(3933.57,2334.61) 3933.57,2382.85 4384.01,2833.29 4399.25,2833.29 4596.66,3030.7 4596.66,3619.66 4828.11,3851.11 J9.1@5030.07,3851.11
AINM3: J14.3 U3.62 | length 1842.7
  Top Layer w7: U3.62@3313.22,2330.67 3360.47,2330.67 3381.26,2351.45 3384.65,2351.45 3395.09,2361.9 3403.89,2361.9 3439.08,2397.08 v2(4042.83,2397.08)
  Signal Layer 2 w7: v2(4042.83,2397.08) 4339.45,2693.71 J14.3@5005.59,2693.71
AINM4: R62.2 R63.2 U3.64 | length 1075
  Top Layer w7: v2(3279.04,2362.95) 3279.8,2362.18 U3.64@3313.22,2362.17
  Top Layer w10: v2(3897.41,1731.68) 3897.98,1731.12 3926.24,1731.12 R63.2@3926.8,1730.55
  Signal Layer 2 w7: v2(3279.04,2362.95) 3279.04,2225.85 3429.42,2075.47 3588.74,2075.47 3897.41,1766.79 v2(3897.41,1731.68)
  Bottom Layer w10: v2(3897.41,1731.68) 3897.98,1731.12 3926.24,1731.12 R62.2@3926.8,1730.55
AINM5: C64.1 R6.2 R41.1 U3.2 | length 2780.2
  Top Layer w7: U3.2@3261.06,2398.58 3261.06,2423.85 3288.24,2451.03 v2(3288.24,2453.18)
  Top Layer w10: v2(3420.1,4320) 3420.1,4350.25 R6.2@3421.1,4351.25
  Signal Layer 2 w7: v2(3288.24,2453.18) 3324.61,2489.55 3718.31,2489.55 4003.64,2774.88 4003.64,3503.74 3962.58,3544.79 v2(3941.83,3544.79)
  Signal Layer 3 w7: v2(3420.1,4320) 3690.97,4049.13 3690.97,3795.65 v2(3941.83,3544.79)
  Bottom Layer w10: v2(3941.83,3544.79) 3941.52,3544.47 3941.52,3518.49 3946.52,3513.49 R41.1@3948.02,3513.49
AINM6: C65.1 R12.2 R53.1 U3.4 | length 2409.8
  Top Layer w7: U3.4@3229.38,2399 3229.38,2446.72 v2(3243.8,2461.15)
  Top Layer w10: v2(3420.1,3889.9) 3420.1,3913.42 R12.2@3421.1,3914.42
  Signal Layer 2 w7: v2(3243.8,2461.15) 3245.53,2462.87 3245.53,2475.1 3272.97,2502.55 3712.92,2502.55 3990.64,2780.26 3990.64,3259.8 3964.81,3285.62 3948.54,3285.62 v2(3946.81,3287.34)
  Signal Layer 3 w7: v2(3420.1,3889.9) 3488.3,3889.9 3946.47,3431.73 3946.47,3287.68 v2(3946.81,3287.34)
  Bottom Layer w10: C65.1@3946.07,3284.95 3946.07,3260.16 3951.07,3255.16 R53.1@3953.45,3255.16 ; C65.1@3946.22,3287.93 v2(3946.81,3287.34)
AINM7: C66.1 R15.2 R57.1 U3.6 | length 2762.6
  Top Layer w7: v2(3191.93,2453.18) 3191.93,2425.05 3198.07,2418.91 U3.6@3198.07,2398.58
  Top Layer w10: v2(3898.6,4323.34) 3898.6,4350.39 R15.2@3899.6,4351.39
  Signal Layer 2 w7: v2(3191.93,2453.18) 3276.25,2537.5 3729.49,2537.5 3924.64,2732.65 3924.64,2739.01 v2(3951.33,2765.71)
  Signal Layer 3 w7: v2(3898.6,4323.34) 3898.6,4180.11 3741.95,4023.45 3741.95,3814.06 3985.21,3570.8 3985.21,2778.18 3971.45,2764.42 3952.62,2764.42 v2(3951.33,2765.71)
  Bottom Layer w10: v2(3951.33,2765.71) C66.1@3952.81,2765.71 ; C66.1@3952.81,2764.12 3952.81,2791.26 R57.1@3956.27,2794.72
AINM8: R44.2 R45.2 U3.8 | length 967.9
  Top Layer w7: v2(3163.54,2364.4) 3163.54,2366.37 3166.57,2369.4 U3.8@3166.57,2398.58
  Top Layer w10: v2(3666.97,1731.68) R45.2@3697.27,1731.68
  Signal Layer 2 w7: v2(3163.54,2364.4) 3163.54,2362.28 3178.04,2347.78 3178.04,2275.41 3169.91,2267.28 3169.91,2260.2 3178.73,2251.38 3178.73,2236.04 3190.4,2224.37 3205.74,2224.37 3217.92,2212.18 3217.92,2196.84 3229.68,2185.09 3245.02,2185.09 3256.78,2173.33 3256.78,2131.85 3655.88,1732.75 3665.9,1732.75 v2(3666.97,1731.68)
  Bottom Layer w10: v2(3666.97,1731.68) R44.2@3697.27,1731.68
AINM9: R70.2 TP18.1 U3.10 | length 3450
  Top Layer w7: U3.10@3135.08,2398.58 3135.08,2456.55 3139.59,2461.06 v2(3139.59,2463.5)
  Signal Layer 3 w7: TP18.1@2149.07,4298.34 2149.07,4212.33 2697.39,3664 3382.05,3664 v2(3826.48,3219.57) 3824.76,3217.85 3818.53,3217.85 3796.35,3195.67 ; v2(3139.59,2463.5) 3139.59,2521.39 3327.34,2709.14 3327.34,2728.17 3354.06,2754.88 3592.85,2754.88 3665.43,2827.46 3665.43,3064.77 3796.32,3195.67
  Bottom Layer w10: v2(3826.48,3219.57) 3826.73,3219.32 3850.49,3219.32 R70.2@3850.74,3219.07
AINM10: R71.2 TP19.1 U3.12 | length 2956.5
  Top Layer w7: v2(3101.9,2440.49) 3103.56,2438.83 U3.12@3103.58,2398.58
  Signal Layer 2 w10: TP19.1@2435.98,4298.34 2566.3,4298.34 3144.64,3720 3412.99,3720 3743.96,3389.03 3743.96,3308.59 3741.96,3306.59 v2(3741.96,3224.53)
  Signal Layer 3 w7: v2(3101.9,2440.49) 3101.47,2440.93 3101.47,2520.67 3393.31,2812.52 3414.7,2812.52 3495.17,2892.99 3495.17,2959.65 3619.57,3084.05 3619.57,3104.07 3740.03,3224.53 v2(3741.96,3224.53)
  Bottom Layer w7: v2(3741.96,3224.53) v2(3741.96,3224.53) R71.2@3742.43,3223.99
AINM11: R72.2 TP20.1 U3.14 | length 3090.9
  Top Layer w7: U3.14@3072.08,2398.58 3072.08,2415.51 3072.19,2415.61 3072.19,2427.56 3070.95,2428.8 3070.95,2477.25 3131.68,2537.98 v2(3202.47,2537.98)
  Signal Layer 2 w7: TP20.1@2713.15,4298.34 2713.15,4226.42 3132.19,3807.38 3436.23,3807.38 3798.82,3444.79 3798.82,2854.45 3772.59,2828.21 v2(3772.59,2815.29)
  Signal Layer 3 w7: v2(3202.47,2537.98) 3326.66,2662.18 3697.98,2662.18 3772.59,2736.78 v2(3772.59,2815.29)
  Bottom Layer w10: R72.2@3770.28,2815.29 v2(3772.59,2815.29)
AINM12: R48.2 R49.2 U3.16 | length 1355.5
  Top Layer w7: v2(3033.5,2440.15) 3033.5,2436.51 3040.59,2429.43 U3.16@3040.59,2398.58
  Top Layer w10: v2(3665.07,1531.68) R49.2@3697.27,1531.68
  Signal Layer 2 w7: v2(3033.5,2440.15) 3015.24,2440.15 2998.26,2423.17 2998.26,2135.84 3602.42,1531.68 v2(3665.07,1531.68)
  Bottom Layer w10: v2(3665.07,1531.68) R48.2@3697.27,1531.68
AINP1: J8.1 U3.57 | length 2507.6
  Top Layer w7: U3.57@3313.64,2251.93 3352.01,2251.93 3363.19,2263.11 3386.11,2263.11 v2(3387.63,2261.58)
  Signal Layer 2 w7: v2(3387.63,2261.58) 3414.65,2234.56 3655.38,2234.56 3907.57,2486.76 3907.57,2527.74 4043.21,2663.38 4043.21,3608.7 J8.1@4477.79,4043.27
AINP2: J9.3 U3.59 | length 2769.4
  Top Layer w7: U3.59@3313.22,2283.43 3337.26,2283.43 3345.06,2291.23 3376.19,2291.23 3397.41,2312.45 3949.6,2312.45 v2(3951.07,2310.98)
  Signal Layer 2 w7: v2(3951.07,2310.98) 3951.07,2357.86 4400.81,2807.6 4554.73,2807.6 4708.66,2961.52 4708.66,3671.55 4788.22,3751.11 J9.3@5030.07,3751.11
AINP3: J14.1 U3.61 | length 2018.8
  Top Layer w7: U3.61@3313.22,2314.92 3331.98,2314.92 3334.29,2317.23 3365.42,2317.23 3386.64,2338.45 3696.36,2338.45 3730.65,2372.74 v2(4026.13,2372.74)
  Signal Layer 2 w7: v2(4026.13,2372.74) 4743.99,2372.74 5047.57,2676.32 5047.57,2711.1 5005.59,2753.08 J14.1@5005.59,2793.71
AINP4: R60.2 R61.2 U3.63 | length 1081.8
  Top Layer w7: U3.63@3313.22,2346.42 3350.6,2346.42 3373.49,2369.31 3375.33,2369.31 3382.95,2376.94 v2(3385.39,2376.94)
  Top Layer w10: v2(3897.41,1832.72) 3897.98,1832.15 3926.24,1832.15 R61.2@3926.8,1831.59
  Signal Layer 2 w7: v2(3385.39,2376.94) 3385.39,2374.5 3313.22,2302.34 3313.22,2210.05 3434.81,2088.47 3641.67,2088.47 v2(3897.41,1832.72)
  Bottom Layer w10: v2(3897.41,1832.72) 3897.98,1832.15 3926.24,1832.15 R60.2@3926.8,1831.59
AINP5: C64.2 R5.2 R31.1 U3.1 | length 2982.6
  Top Layer w7: R5.2@3274.15,4351.25 3280.65,4344.75 3290.09,4344.75 3639.62,3995.22 3639.62,3772.72 3867.55,3544.79 v2(3901.23,3544.79) ; U3.1@3276.81,2398.58 3276.81,2417.28 3298.61,2439.08 3327.09,2439.08 v2(3328.63,2440.62)
  Signal Layer 2 w7: v2(3328.63,2440.62) 3328.81,2440.8 3697.33,2440.8 3810.45,2553.93 3898.21,2553.93 4016.64,2672.36 4016.64,3515.48 3965.26,3566.86 3923.31,3566.86 v2(3901.23,3544.79)
  Bottom Layer w10: R31.1@3892.6,3513.49 3896.52,3513.49 3901.52,3518.49 3901.52,3545.07 v2(3901.23,3544.79)
AINP6: C65.2 R11.2 R37.1 U3.3 | length 2347.7
  Top Layer w7: U3.3@3245.31,2398.58 3245.31,2426.49 3269.58,2450.76 v2(3269.58,2470.87)
  Top Layer w10: v2(3274.15,3890) R11.2@3274.15,3914.42
  Signal Layer 3 w7: v2(3269.58,2470.87) 3329.13,2530.43 3745.63,2530.43 3826.48,2611.28 3826.48,2909.66 3835.13,2918.31 3835.13,3104.81 3843.98,3113.67 3843.98,3237.88 v2@3885.14,3279.04 ; v2(3274.15,3890) 3305.06,3890 3885.28,3309.78 v2(3885.28,3282.02)
  Bottom Layer w10: v2(3885.28,3282.02) 3886.43,3283.17 3903.72,3283.17 3906.22,3285.67 C65.2@3906.22,3287.93 ; R37.1@3901.58,3254.71 3906.07,3259.2 C65.2@3906.07,3282.69
AINP7: C66.2 R14.2 R54.1 U3.5 | length 2647.3
  Top Layer w7: U3.5@3213.58,2399 3213.58,2492.66 3242.61,2521.68 3242.61,2530.01 v2(3244.33,2531.74)
  Top Layer w10: v2(3759.45,4323.34) 3759.45,4349.8 R14.2@3761.04,4351.39
  Signal Layer 2 w7: v2(3244.33,2531.74) 3308.59,2595.99 3769.6,2595.99 3911.64,2738.03 v2(3911.64,2764.09) 3884.1,2791.63 3856.42,2791.63 3819.32,2828.72 3819.32,3187.66 3843.98,3212.32 3843.98,4238.81 v2(3759.45,4323.34)
  Bottom Layer w10: R54.1@3906.27,2794.72 3907.81,2794.72 3912.81,2789.72 C66.2@3912.81,2764.12 C66.2@3911.67,2764.12
AINP8: R42.2 R43.2 U3.7 | length 890.9
  Top Layer w7: U3.7@3182.32,2399 3182.32,2378.83 v2(3196.76,2364.4)
  Top Layer w10: v2(3666.97,1832.72) R43.2@3697.27,1832.72
  Signal Layer 2 w7: v2(3196.76,2364.4) 3217.41,2343.74 3217.41,2236.73 3230.11,2224.03 3245.45,2224.03 3339.36,2130.12 3339.36,2067.66 3574.29,1832.72 v2(3666.97,1832.72)
  Bottom Layer w10: v2(3666.97,1832.72) R42.2@3697.27,1832.72
AINP9: R24.2 TP14.1 U3.9 | length 3684.8
  Top Layer w7: U3.9@3150.82,2413.35 3150.82,2428.21 3152.58,2429.96 v2(3152.58,2432.4)
  Signal Layer 2 w7: v2(3152.58,2432.4) 3151.42,2433.55 3134.43,2433.55 3101.44,2466.55 3101.44,2530.43 3319.17,2748.16 3450.11,2748.16 3495.17,2793.22 3495.17,3139.03 3572.62,3216.48 3572.62,3396.92 3560.03,3409.5 v2(3560.03,3526.8)
  Signal Layer 3 w10: TP14.1@2149.07,4563.77 2225,4487.84 2225,4183.02 2728.01,3680 3408.41,3680 3560.03,3528.38 v2(3560.03,3526.8)
  Bottom Layer w10: v2(3560.03,3526.8) 3560.77,3527.53 3801.12,3527.53 R24.2@3801.85,3528.27
AINP10: R25.2 TP16.1 U3.11 | length 3307.3
  Top Layer w7: U3.11@3119.33,2398.58 3119.33,2433.17 3119.4,2433.24 3119.4,2447.74 3119.33,2447.82 3119.33,2472.62 v2(3119.72,2473.01)
  Signal Layer 2 w7: v2(3119.72,2473.01) 3118.94,2473.8 3118.94,2509.16 3255.04,2645.27 3495.1,2645.27 3650.09,2800.26 3650.09,3055.99 3713.95,3119.85 v2(3745.25,3119.85)
  Signal Layer 2 w10: TP16.1@2435.98,4563.77 2570.7,4429.05 2570.7,4316.56 3146.86,3740.4 3429.72,3740.4 3762.96,3407.17 3762.96,3137.56 v2(3745.25,3119.85)
  Bottom Layer w10: v2(3745.25,3119.85) 3745.42,3119.67 R25.2@3745.42,3119.38
AINP11: R22.2 TP15.1 U3.13 | length 3402.9
  Top Layer w7: U3.13@3087.83,2398.58 3087.83,2429.82 3084.4,2433.24 3084.4,2462.72 3115.69,2494.01 3188.53,2494.01 v2(3221.54,2527.01)
  Signal Layer 2 w7: TP15.1@2713.15,4563.77 2713.15,4436.52 2662.15,4385.52 2662.15,4247.74 3118.51,3791.38 3401.37,3791.38 3778.96,3413.79 3778.96,2977.36 3745.25,2943.65 v2(3745.25,2922.58)
  Signal Layer 3 w7: v2(3221.54,2527.01) 3223.26,2528.74 3223.26,2535.42 3333.94,2646.1 3700.29,2646.1 3790.09,2735.9 3790.09,2877.74 v2(3745.25,2922.58)
  Bottom Layer w7: R22.2@3743.96,2920.38 R22.2@3745.42,2921.84
  Bottom Layer w10: R22.2@3743.96,2920.38 3745.25,2921.67 v2(3745.25,2922.58)
AINP12: R46.2 R47.2 U3.15 | length 1187
  Top Layer w7: v2(3040.98,2364.4) 3056.34,2379.75 U3.15@3056.34,2398.58
  Top Layer w10: v2(3666.97,1631.68) R47.2@3697.27,1631.68
  Signal Layer 2 w7: v2(3040.98,2364.4) 3024.64,2348.05 3024.64,2136.85 3529.8,1631.68 v2(3666.97,1631.68)
  Bottom Layer w10: v2(3666.97,1631.68) R46.2@3697.27,1631.68
Board_temp: C110.1 J5.30 R137.1 | length 684.6
  Top Layer w10: v3(3524.77,648.03) 3525.09,648.35 3546.94,648.35 R137.1@3547.26,648.67 ; C110.1@3790.48,172.6 3808.59,172.6 3814.45,178.46 v3(3814.45,362.57)
  Signal Layer 2 w10: v3(3524.77,648.03) 3524.77,573.84 3736.05,362.57 v3(3814.45,362.57)
BOOT1: U1.E13
BOOT2: U1.E9
BOOT3: U1.E6
BOOT4: U1.E2
Bus_voltage_ADC: C111.2 J5.28 R146.1 R147.1 | length 266.5
  Top Layer w10: J5.28@3845.94,313.07 3845.94,201.27 3870.11,177.1 C111.2@3870.11,172.6 3870.52,172.19 3870.52,84.04 R146.1@3870.93,83.63 R147.1@3897.67,83.63
COMP1: D5.2 R3.2 U1.A12 U12.16 | length 925.7
  Top Layer w7: D5.2@2291.59,2887.97 2297.93,2881.63 2297.93,2878.53 2337.78,2838.68 U12.16@2337.78,2831.59
  Top Layer w10: D5.2@2291.59,2887.97 2291.91,2888.3 2291.91,2911.66 2301.49,2921.24 v2(2361.98,2921.24) ; R3.2@2838.42,3214 2875.44,3214 v2(2903.82,3185.62) U1.A12@2919.84,3169.6
  Signal Layer 3 w10: v2(2361.98,2921.24) 2554.75,2921.24 2691.84,3058.33 2776.53,3058.33 v2(2903.82,3185.62)
  Bottom Layer w10: v2@2902.96,3184.76 v2(2903.82,3185.62)
COMP2: D8.2 R9.2 U1.A10 U12.13 | length 790.3
  Top Layer w8: U12.13@2396.83,2831.59 2396.83,2838.68 2432.33,2874.18 2432.33,2882.13 D8.2@2438.17,2887.97 2438.3,2888.1 2459.62,2888.1 v2(2459.75,2888.23)
  Top Layer w10: R9.2@2838.42,3146 2874.52,3146 2893.96,3126.56 2893.96,3112.89 v2(2895.1,3111.74) ; v2@2900.76,3107.71 2918.74,3107.71 U1.A10@2919.84,3106.61
  Signal Layer 3 w8: v2(2459.75,2888.23) 2473.3,2901.78 2782.13,2901.78 2895.1,3014.76 v2(2895.1,3111.74)
  Signal Layer 3 w10: v2@2894.79,3111.43 v2(2895.1,3111.74)
  Bottom Layer w10: v2(2895.1,3111.74) 2895.1,3123.21
COMP3: D7.2 R4.2 U1.A5 U12.9 | length 796.6
  Top Layer w7: U12.9@2422.42,2746.95 2429.51,2746.95 2444.35,2732.1 D7.2@2444.35,2675.99
  Top Layer w10: D7.2@2444.35,2675.99 v2(2473.63,2675.99) ; R4.2@2838.42,2919 2838.42,2923.5 2840.92,2926 2845.42,2926 2851.89,2932.47 2903.18,2932.47 v2(2904.33,2933.62) U1.A5@2919.84,2949.13
  Signal Layer 3 w10: v2(2473.63,2675.99) 2547.94,2750.29 2547.94,2783.86 2621.18,2857.09 2648.59,2857.09 2684.24,2821.45 2792.15,2821.45 v2(2904.33,2933.62)
COMP4: D6.2 R10.2 U1.A3 U12.4 | length 860.8
  Top Layer w7: D6.2@2291.34,2675.66 D6.2@2290.53,2676.48 2290.53,2701.26 2312.18,2722.91 U12.4@2312.18,2746.95
  Top Layer w10: D6.2@2291.34,2675.66 2291.34,2638.48 v2(2292.15,2637.67) ; v2(2817.69,2815.69) 2818.83,2816.84 2818.83,2828.92 2838.42,2848.5 R10.2@2838.42,2853 2887.72,2853 2897.61,2862.9 v2(2899.24,2862.9) 2899.24,2864.22 2919.84,2884.82 U1.A3@2919.84,2886.14
  Signal Layer 2 w10: v2(2292.15,2637.67) 2571.59,2637.67 v2(2709.2,2775.28)
  Bottom Layer w10: v2(2709.2,2775.28) 2749.62,2815.69 v2(2817.69,2815.69)
DAC_CH4: R36.2 R90.1 U5.3 | length 3502.1
  Top Layer w7: R36.2@2750.89,2710.14 2750.89,2600.31 2772.17,2579.03 3242.29,2579.03 3344.82,2476.51 4006.54,2476.51 4415,2068.04 v3(4415,1211.18)
  Top Layer w10: R90.1@2525.69,3134.77 2557.8,3102.65 2557.8,2729.73 2577.39,2710.14 R36.2@2750.89,2710.14 ; U5.3@4414.64,1180.08 4415,1180.44 v3(4415,1211.18)
DAC_CSn: R145.2 R152.1 U4.12 | length 1913.2
  Top Layer w8: R152.1@1557.16,1571.04 v3(1557.33,1571.22) R152.1@1558.3,1572.19 ; v4(2280.64,3090.01) 2282.93,3092.3 2294.49,3092.3 2317.27,3115.08 U4.12@2324.35,3115.08
  Signal Layer 2 w8: v3(1557.33,1571.22) 1600.09,1571.22 1618.16,1589.29 1618.16,2451.48 2256.69,3090.01 v4(2280.64,3090.01)
DAC_OUT1: R28.2 R93.1 | length 296.8
  Top Layer w10: R93.1@2465.05,3239.36 2465.84,3238.57 2481.69,3238.57 2493.83,3250.71 R28.2@2756.5,3250.71
DAC_OUT2: R34.2 R92.1 | length 156.8
  Top Layer w10: R92.1@2526.12,3196.61 2576.28,3196.61 2621.15,3151.74 R34.2@2664.31,3151.74
DAC_OUT3: R52.2 R91.1 | length 324.9
  Top Layer w10: R91.1@2525.69,3165.64 2545.31,3165.64 2576.9,3134.05 2576.9,2944.1 2613.23,2907.77 2625.68,2907.77 2628.18,2905.27 R52.2@2628.18,2902.01
DAC_OUT5: R51.2 R94.1 R186.2 | length 2993.9
  Top Layer w10: R94.1@2293.69,3240.42 2242.58,3240.42 2178.45,3176.29 2178.45,2787.07 2213.01,2752.52 2234.86,2752.52 2237.36,2750.02 R186.2@2237.36,2745.52 2237.36,2665.59 2286.54,2616.41 2422.34,2616.41 2536.48,2502.27 2536.48,2124.41 v3(2669.83,1991.06) ; v3(3669.94,1311.18) R51.2@3697.27,1311.18
  Signal Layer 2 w7: v3(2669.83,1991.06) 3095.76,1991.06 3377.64,1709.17 3377.64,1603.48 v3(3669.94,1311.18)
DAC_OUT6: R95.1 R183.2 | length 408.3
  Top Layer w10: R183.2@2236.22,2831.36 2236.22,2979.53 2194.45,3021.3 2194.45,3162.47 2224.15,3192.16 2238.29,3192.16 2240.79,3194.66 R95.1@2240.79,3194.87
DAC_OUT7: R96.1 R185.2 | length 587
  Top Layer w10: R96.1@2240.9,3161.7 2216.31,3161.7 2210.45,3155.84 2210.45,3034.53 2279.5,2965.49 2438.37,2965.49 2493.63,2910.23 R185.2@2493.63,2812.05
DAC_OUT8: R97.1 R184.2 | length 600
  Top Layer w10: R97.1@2240.64,3129.43 2240.64,3036.61 2295.75,2981.49 2461.9,2981.49 2525.8,2917.59 2525.8,2791.39 R184.2@2496.06,2761.65 ; R184.2@2493.63,2764.07 R184.2@2493.63,2768.57
DAC_OUT_BI4: R50.2 R101.2 U5.1 | length 1005.4
  Top Layer w10: v3(3669.94,1412.22) R50.2@3697.27,1412.22 ; v3(4358.3,1334.43) 4359.92,1332.82 4359.92,1244.78 R101.2@4361.54,1243.16 4361.54,1149.91 4399.36,1112.09 4407.83,1112.09 U5.1@4414.64,1105.28
  Bottom Layer w10: v3(3669.94,1412.22) 3703.25,1378.92 4313.82,1378.92 v3(4358.3,1334.43)
DAC_OUT_BI_header: J1.1 R50.1 | length 1743.5
  Top Layer w10: R50.1@3737.27,1412.22 v3(3761.88,1412.22)
  Signal Layer 2 w10: v3(3761.88,1412.22) 4332.84,1412.22 5113.2,631.86 5113.2,596.7 J1.1@5119.67,590.24
DAC_OUT_I_CLAMP: J1.3 R51.1 | length 1765.1
  Top Layer w10: R51.1@3737.27,1311.18 v3(3761.88,1311.18)
  Signal Layer 2 w10: v3(3761.88,1311.18) 3840.88,1232.18 4450.44,1232.18 4978.91,703.72 4978.91,631 J1.3@5119.67,490.24
DAC_REFOUT: R98.1 U4.1 | length 3264.5
  Top Layer w7: U4.1@2434.59,3115.08 2435.06,3114.61 2455.4,3114.61 2541.8,3028.21 2541.8,2713.2 2696.08,2558.93 3244.01,2558.93 3344.82,2458.12 4006.54,2458.12 4102.3,2362.36 v3@4102.3,1291.09 ; v3(4102.3,1290.18) v3@4102.3,1291.09 ; R98.1@4130.54,1291.18 4130.49,1291.13 4102.35,1291.13 v3@4102.3,1291.09
DAC_SCLK: R144.2 R151.1 U4.13 | length 1966.5
  Top Layer w8: R151.1@1557.16,1521.49 R151.1@1559.36,1523.7 ; v4(2336.2,3063.83) 2338.49,3066.13 2338.49,3070.56 2349.94,3082.01 U4.13@2349.94,3089.49
  Signal Layer 2 w8: v3(1556.18,1521.75) 1601.42,1521.75 1635.31,1555.65 1635.31,2431.78 2267.37,3063.83 v4(2336.2,3063.83)
DAC_SDI: R142.2 R154.1 U4.14 | length 1851.2
  Top Layer w8: R154.1@1557.16,1670.16 1557.33,1670.33 v3(1720,1670.33) ; v4(2357.46,3052.2) 2357.46,3054.37 2369.35,3066.26 2369.35,3089.21 U4.14@2369.63,3089.49
  Signal Layer 2 w8: v3(1720,1670.33) 1720,2414.74 v4(2357.46,3052.2)
  other v3: 1557.43,1670.33
DAC_SDO: R143.2 R163.1 U4.15 | length 1424
  Top Layer w7: R163.1@1557.16,2116.16 v3(1738,2116.16)
  Top Layer w8: v4(2386.79,3054.82) 2389.04,3057.06 2389.04,3089.21 U4.15@2389.31,3089.49
  Signal Layer 2 w7: v3(1738,2116.16) 1738,2118.59 1749.07,2129.66 1749.07,2136.2 2058.4,2445.52 2058.4,2726.42 v4(2386.79,3054.82)
  other v3: 1556.18,2115.19
EN4_header: J2.6 R65.1 | length 1916.6
  Top Layer w7: R65.1@3966.8,1630.55 3966.8,1563.48 3991.22,1539.07 3991.22,950.9 4233.72,708.4 4748.69,708.4 4829.24,627.86 4829.24,432.22 J2.6@4871.22,390.24
EN4_powerSch: R64.1 U1.E1 | length 1887.7
  Top Layer w7: U1.E1@3045.91,2823.98 3046.38,2823.98 v3(3061.49,2839.09)
  Signal Layer 2 w7: v3(3061.49,2839.09) 3061.49,2817.64 3106.42,2772.71 3106.42,2570.21 3084.4,2548.2 3084.4,2433.24 3099.3,2418.35 3099.3,2314.78 3087.63,2303.11 3072.29,2303.11 3060.61,2291.44 3060.61,2275.41 3072.29,2263.74 3087.63,2263.74 3099.47,2251.9 3099.47,2236.56 3111.4,2224.63 3126.74,2224.63 3138.71,2212.65 3138.71,2197.32 3150.71,2185.32 3166.05,2185.32 3178.73,2172.64 3178.73,2157.3 3263.77,2072.26 3297.98,2072.26 3676.48,1693.77 3925.09,1693.77 v2(3988.3,1630.55)
  Bottom Layer w10: R64.1@3966.8,1630.55 v2(3988.3,1630.55)
EN_DCDC1: R129.1 R149.1 U1.E14 | length 2538.5
  Top Layer w7: R149.1@1557.16,1422.38 R149.1@1559.19,1424.41
  Top Layer w10: U1.E14@3045.82,3232.43 3045.82,3231.59 3054.8,3222.61 v3@3054.8,3221.61
  Signal Layer 2 w7: v3(1556.18,1421.41) 1727,1421.41 2970.53,2664.94 2970.53,2815.19 2988.19,2832.85 2988.19,3152.78 v3(3056.42,3221)
EN_DCDC2: R130.1 R150.1 U1.E8 | length 2951.3
  Top Layer w7: R150.1@1557.16,1471.93 R150.1@1559.36,1474.14 ; U1.E8@3045.91,3044.46 3045.91,3044.15 3061.96,3028.09 v3(3061.96,3027.78)
  Signal Layer 2 w7: v4(2771.66,2381.03) 2773.66,2381.03 2983.53,2590.9 2983.53,2652.46 3001.19,2670.12 3001.19,2873.48 3046.11,2918.39 3046.11,2973.77 3043.6,2976.29 3043.6,3009.42 v3(3061.96,3027.78)
  Signal Layer 3 w7: v3@1557.16,1471.54 1618.16,1532.54 1618.16,2379.16 1701.48,2462.48 2521.26,2462.48 2602.7,2381.03 v4(2771.66,2381.03)
  other v3: 1557.29,1472.07
EN_DCDC3: R131.1 R164.1 U1.E7 | length 2328.4
  Top Layer w7: R164.1@1558.11,2174.6 v3(1738,2174.6) ; U1.E7@3045.91,3012.93 v3@3061.59,2997.24
  Signal Layer 2 w7: v4(2771.66,2355.03) 2870.2,2355.03 2996.53,2481.36 2996.53,2623.53 3043.99,2670.99 3043.99,2872.09 3059.11,2887.21 3059.11,2924.27 3081.11,2946.27 3081.11,2976.73 v3(3061.1,2996.75)
  Signal Layer 3 w7: v3(1738,2174.6) 1738,2393.44 1764.51,2419.95 2269.3,2419.95 2334.22,2355.03 v4(2771.66,2355.03)
  other v3: 1557.14,2173.63
EN_DCDC4: R64.2 R65.2 R132.1 R170.2 R177.2 R178.1 | length 2883.4
  Top Layer w10: R178.1@1557.16,1036.74 R177.2@1557.16,1075.74 R170.2@1557.16,1136.86 ; v2(3899.32,1630.55) R65.2@3926.8,1630.55
  Signal Layer 3 w10: v3(1556.18,1135.89) 3712.48,1135.89 3833.47,1256.89 3833.47,1492.12 3899.32,1557.97 v2(3899.32,1630.55)
  Bottom Layer w10: v2(3899.32,1630.55) R64.2@3926.8,1630.55
EN_RLY1: Q1.1 R133.1 R165.1 | length 4717.8
  Top Layer w10: Q1.1@4767.49,3948.8 4767.58,3948.71 4767.58,3914.52 v4(4767.67,3914.42)
  Signal Layer 3 w7: v4(3958.11,2083.7) 3958.11,2107.12 4591.97,2740.98 4591.97,3738.72 v4(4767.67,3914.42)
  Bottom Layer w7: R133.1@1557.16,2215.27 1558.13,2216.24 1730,2216.24 1803.76,2216.24 1892.19,2127.81 2776.07,2127.81 2834.03,2069.84 2925.21,2069.84 2985.01,2010.05 3884.46,2010.05 v4(3958.11,2083.7)
  other v3: 1556.18,2214.3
